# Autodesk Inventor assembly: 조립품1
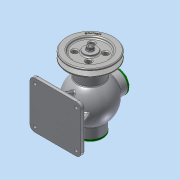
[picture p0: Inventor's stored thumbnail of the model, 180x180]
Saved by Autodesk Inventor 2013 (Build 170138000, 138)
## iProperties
Created: 2018-06
Part Number: 조립품1
Document SubType Name: Assembly
Designer: Administrator
Author: Administrator
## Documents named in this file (19)
- C:\Users\Administrator\Desktop\480612V1006\조립품1.iam
- C:\Users\Administrator\Desktop\480612V1006\본체.ipt
- C:\Users\Administrator\Desktop\480612V1006\V-벨트풀리.ipt
- C:\Users\Administrator\Desktop\480612V1006\너트 M8.ipt
- C:\Users\Administrator\Desktop\480612V1006\뒤커버.ipt
- C:\Users\Administrator\Desktop\480612V1006\멈춤링 15x1.ipt
- C:\Users\Administrator\Desktop\480612V1006\멈춤링 35x1.6.ipt
- 멈춤링 35x1.6.ipt
- C:\Users\Administrator\Desktop\480612V1006\베어링 6202.ipt
- 베어링 6202.ipt
- C:\Users\Administrator\Desktop\480612V1006\볼트 M4x12.ipt
- C:\Users\Administrator\Desktop\480612V1006\볼트 M4x16.ipt
- C:\Users\Administrator\Desktop\480612V1006\부시.ipt
- C:\Users\Administrator\Desktop\480612V1006\상부커버.ipt
- C:\Users\Administrator\Desktop\480612V1006\슬라이드.ipt
- C:\Users\Administrator\Desktop\480612V1006\앞커버.ipt
- C:\Users\Administrator\Desktop\480612V1006\오일 실 15 30 7.ipt
- C:\Users\Administrator\Desktop\480612V1006\키 4x4x12.ipt
- C:\Users\Administrator\Desktop\480612V1006\편심축.ipt
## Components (1 placed, 1 different names)
1. V-벨트풀리:1
